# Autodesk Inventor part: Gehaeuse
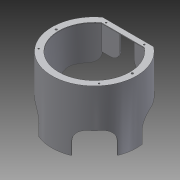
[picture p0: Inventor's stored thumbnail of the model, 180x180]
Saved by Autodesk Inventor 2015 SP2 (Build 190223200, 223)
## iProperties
Created: 2015-09
Part Number: Gehaeuse
Material: PC/ABS-Kunststoff
Document SubType Name: Modeling
Designer: ryll
Mass: 48.301 g
Surface Area: 1814.76 cm^2
Volume: 135.194 cm^3
Density: 0.357273 g/cm^3
Appearance: Glatt - weiß
Author: ryll
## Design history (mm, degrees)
sketch "Skizze1"
  geometry: L1 (53.666, 71)-(-53.666, 71); A1 r 89 centre (0, 0) between (-53.666, 71) and (53.666, 71); 1 further point
  constraints: 2 end point, 2 point on circle, 1 centre point, 1 coincident, 1 horizontal
  dimensions: "d0" = 178 diameter of A1; "d1" = 71 distance from line of point (0, 0) L1
extrude "Extrusion1" new body sketch "Skizze1" distance "d2" = 1.5; taper "d3" = 0 deg
sketch "Skizze2"
  geometry: L1 (-53.666, 71)-(-52.46, 69.404); L2 (53.666, 71)-(52.46, 69.404); L3 (-53.666, 71)-(0, 0); L4 (0, 0)-(53.666, 71); A1 r 89 centre (0, 0) between (-53.666, 71) and (53.666, 71); A2 r 87 centre (0, 0) between (-52.46, 69.404) and (52.46, 69.404); 1 further point
  constraints: 8 end point, 2 centre point, 2 point on circle, 2 point on line
  dimensions: "d4" = 2 radial gap between concentric circles of A1 A2
extrude "Extrusion2" join sketch "Skizze2" distance "d5" = 80; taper "d6" = 0 deg
sketch "Skizze3"
  geometry: L1 (0, 1.5)-(107.331, 1.5) reference; L2 (107.331, 1.5)-(107.331, 61.5); L3 (107.331, 61.5)-(93.459, 61.5); L4 (93.459, 61.5)-(63.666, 36.5); L5 (63.666, 36.5)-(43.666, 36.5); L6 (43.666, 36.5)-(13.872, 61.5); L7 (13.872, 61.5)-(0, 61.5); L8 (0, 61.5)-(0, 1.5); L9 (53.666, 1.5)-(53.666, 110.894); L10 (93.666, 21.5)-(13.666, 21.5); L11 (93.666, 31.5)-(13.666, 31.5); L12 (13.666, 11.5)-(93.666, 11.5); A1 r 10 centre (93.666, 21.5) between (93.666, 11.5) and (93.666, 31.5); A2 r 10 centre (13.666, 21.5) between (13.666, 31.5) and (13.666, 11.5); 1 further point
  constraints: 24 end point, 4 point on circle, 4 tangent, 2 centre point, 2 horizontal, 2 parallel, 2 point on line, 1 midpoint, 1 perpendicular, 1 symmetric about line, 1 vertical, 1 other
  dimensions: "d7" = 60 distance of L1.end L2.end; "d8" = 100 deg angle of L6 L4; "d9" = 35 distance between parallel lines of L1 L5; "d10" = 20 distance of L4.end L5.end; "d43" = 80 distance of L10.start L10.end; "d44" = 20 distance between parallel lines of L11 L12; "d45" = 10 distance between parallel lines of L1 L12
extrude "Extrusion3" join sketch "Skizze3" distance "d11" = 1.5; taper "d12" = 0 deg
sketch "Skizze4"
  geometry: L1 (-80, 0)-(80, 0); L2 (0, 103)-(0, -121) reference; 3 further points
  constraints: 2 coincident, 2 end point, 1 horizontal, 1 midpoint, 1 symmetric about line
  dimensions: "d13" = 160 distance of L1.start L1.end
hole "Bohrung1" sketch "Skizze4" at (-80, 0), (80, 0) diameter "d14" = 4.2; stored, may be unused: countersink angle "d18" = 90 deg, drill point angle "d20" = 118 deg; dims "d15" = 6, "d16" = 4, "d17" = 2, "d19" = 8
sketch "Skizze5"
  geometry: L1 (0, 103)-(0, -121) reference; L2 (-124.6, 0)-(124.6, 0) reference; L3 (-40, 65)-(40, 65); L4 (0, 0)-(63.582, -53.351); L5 (0, 0)-(-63.582, -53.351); A1 r 83 centre (0, 0) between (63.582, -53.351) and (-63.582, -53.351); 5 further points
  constraints: 6 end point, 5 coincident, 2 point on circle, 1 centre point, 1 horizontal, 1 midpoint, 1 point on line, 1 symmetric about line
  dimensions: "d21" = 166 diameter of A1; "d22" = 40 deg angle of L5 L2; "d23" = 40 deg angle of L2 L4 (= d22); "d24" = 65 distance between parallel lines of L2 L3; "d25" = 80 distance of L3.start L3.end
hole "Bohrung2" sketch "Skizze5" at (40, 65), (-40, 65), (-63.582, -53.351), (63.582, -53.351) diameter "d26" = 3.1; stored, may be unused: countersink angle "d30" = 90 deg, drill point angle "d32" = 118 deg; dims "d27" = 6, "d28" = 4, "d29" = 2, "d31" = 8
sketch "Skizze6"
  geometry: L1 (53.666, 71)-(52.46, 69.404) reference; L2 (-52.46, 69.404)-(-53.666, 71) reference; L3 (0, 0)-(-88.134, 12.386); L4 (0, 0)-(-82.519, -33.34); L5 (0, 0)-(-34.059, -82.225); L6 (0, 0)-(34.059, -82.225); L7 (0, -121)-(0, 103) reference; L8 (-127.601, 0)-(127.601, 0) reference; L9 (-88.134, 12.386)-(-86.153, 12.108); L10 (-80.665, -32.591)-(-82.519, -33.34); L11 (-34.059, -82.225)-(-33.293, -80.378); L12 (33.293, -80.378)-(34.059, -82.225); L13 (0, 0)-(88.134, 12.386); L14 (0, 0)-(82.519, -33.34); L15 (86.153, 12.108)-(88.134, 12.386); L16 (80.665, -32.591)-(82.519, -33.34); A1 r 89 centre (0, 0) between (-53.666, 71) and (53.666, 71) reference; A2 r 87 centre (0, 0) between (-52.46, 69.404) and (52.46, 69.404) reference; A3 r 87 centre (0, 0) between (-52.46, 69.404) and (52.46, 69.404) reference; A4 r 89 centre (0, 0) between (-53.666, 71) and (53.666, 71) reference; A5 r 89 centre (0, 0) between (82.519, -33.34) and (88.134, 12.386); A6 r 87 centre (0, 0) between (80.665, -32.591) and (86.153, 12.108); A7 r 87 centre (0, 0) between (-33.293, -80.378) and (33.293, -80.378); A8 r 89 centre (0, 0) between (-88.134, 12.386) and (-82.519, -33.34); A9 r 87 centre (0, 0) between (-86.153, 12.108) and (-80.665, -32.591); A10 r 89 centre (0, 0) between (-34.059, -82.225) and (34.059, -82.225); 1 further point
  constraints: 29 point on circle, 24 end point, 8 point on line, 6 centre point, 4 coincident, 4 collinear, 1 symmetric about line
  dimensions: "d34" = 45 deg angle of L6 L5; "d35" = 30 deg angle of L14 L13 (= d39); "d38" = 8 deg angle of L3 L8; "d39" = 30 deg angle of L4 L3; "d40" = 8 deg angle of L8 L13 (= d38)
extrude "Extrusion4" join sketch "Skizze6" distance "d36" = 50; taper "d37" = 0 deg
sketch "Skizze7"
  geometry: L1 (107.331, 1.5)-(107.331, 81.5) reference; L2 (0, 1.5)-(107.331, 1.5) reference; L3 (0, 1.5)-(0, 81.5) reference; L4 (107.331, 1.5)-(68.666, 1.5); L5 (68.666, 1.5)-(68.666, 61.5); L6 (68.666, 61.5)-(107.331, 61.5); L7 (107.331, 61.5)-(107.331, 1.5); L8 (0, 1.5)-(38.666, 1.5); L9 (38.666, 1.5)-(38.666, 61.5); L10 (38.666, 61.5)-(0, 61.5); L11 (0, 61.5)-(0, 1.5); L12 (53.666, 1.5)-(53.666, 81.5)
  constraints: 18 end point, 4 parallel, 2 horizontal, 2 perpendicular, 1 collinear, 1 vertical, 1 other
  dimensions: "d46" = 60 distance of L4.end L5.end; "d49" = 30 distance between parallel lines of L9 L5
extrude "Extrusion5" join sketch "Skizze7" distance "d47" = 2; taper "d48" = 0 deg
fillet "Rundung1" dims "d41" = 25
fillet "Fillet2" dims "d42" = 2
fillet "Rundung3" dims "d50" = 20
fillet "Rundung4" dims "d51" = 5
sketch "Skizze8"
  geometry: L1 (45, 60)-(-45, 60); A1 r 75 centre (0, 0) between (-45, 60) and (45, 60); 1 further point
  constraints: 2 end point, 2 point on circle, 1 centre point, 1 coincident, 1 horizontal
  dimensions: "d52" = 60 distance from line of L1 point (0, 0); "d53" = 75 radius of A1
extrude "Extrusion6" cut sketch "Skizze8" stored distance "d54" = 2; taper "d55" = 0 deg
node "Volumenkörper1"
node "Projizierte Kontur2"
